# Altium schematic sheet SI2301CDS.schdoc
size 127 x 101 mm
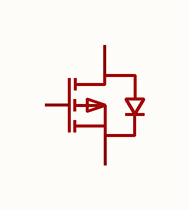
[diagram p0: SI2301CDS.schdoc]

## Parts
Q?  si2301cds  [SOT-23-3_L2.9-W1.3-P1.90-LS2.4-BR]  (value not drawn)

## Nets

Not connected (* = marked no-connect by the designer): Q? 1(G) 2(S) 3(D)

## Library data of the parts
Q? = si2301cds: 数量:1个P沟道;漏源电压(Vdss):20V;连续漏极电流(Id):3A;导通电阻(RDS(on)):110mΩ@4.5V;耗散功率(Pd):1W;阈值电压(Vgs(th)):1V;; Manufacturer: TECH PUBLIC(台舟); AddInBom: yes; ModelId: c62791f0466c4ae2a892c056b845b0ca; ModelName: SOT-23-3P_L2.9-W1.3-H1.0-LS2.4-P0.95; ModelTransform: 98.425,114.173,0,180,0,0,0.0005,-0.0005,0; Number: 1个P沟道; Drain to Source Voltage: 20V; Current - Continuous Drain(Id): 3A; Pd - Power Dissipation: 1W; Gate Threshold Voltage (Vgs(th)): 1V; Gate Charge(Qg): 12nC; Input Capacitance(Ciss): 405pF; Reverse Transfer Capacitance (Crss@Vds): 55pF; Type: P沟道; Output Capacitance(Coss): 75pF; Vgs: ±12V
